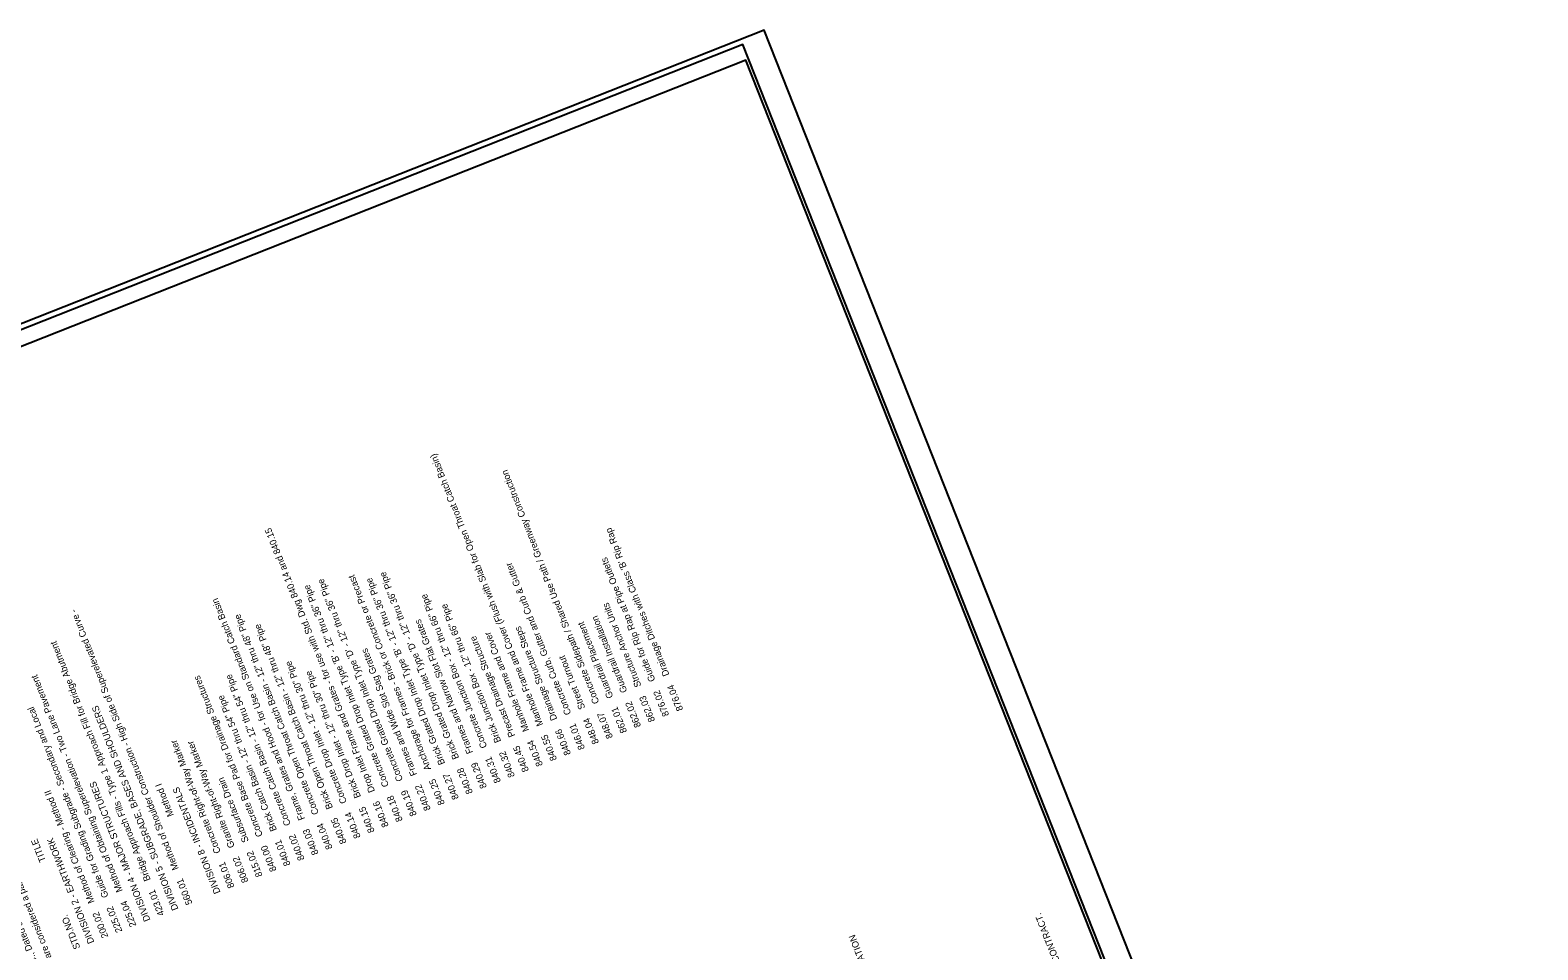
# Model space of a CAD drawing. Extents: x 1247235 to 1260080, y 742320 to 754020.
# Drawn here: x 1254628 to 1260080, y 750692 to 754020 of the extents above; entities that cross this region are included whole.
import ezdxf

# ---------------------------------------------------------------- set-up
doc = ezdxf.new("R2010")
doc.units = 0
for name, color, linetype in [('Scratch_Level_2', 7, 'Continuous'), ('Sheet Data Text CELL', 7, 'Continuous'), ('Sheet Plan CELL', 7, 'Continuous'), ('Sheet Plot Border Inside CELL', 7, 'Continuous'), ('Sheet Plot Border Outside CELL', 7, 'Continuous')]:
    doc.layers.add(name, color=color, linetype=linetype)

msp = doc.modelspace()

# ---------------------------------------------------------------- linework, layer by layer
at = {"layer": 'Scratch_Level_2'}
msp.add_line((1258461.9, 750758.6), (1257215.2, 753911.5), dxfattribs=at)
at = {"layer": 'Sheet Plan CELL'}
msp.add_lwpolyline([(1252801.2, 752166.1), (1255294.6, 745860.4), (1259708.5, 747605.8), (1257215.2, 753911.5)], close=True, dxfattribs=at)
at = {"layer": 'Sheet Plot Border Inside CELL'}
msp.add_lwpolyline([(1259974.2, 746964.6), (1257204.9, 753968.2), (1252769.9, 752214.5), (1255539.2, 745211)], close=True, dxfattribs=at)
at = {"layer": 'Sheet Plot Border Outside CELL'}
msp.add_lwpolyline([(1260079.9, 746943.2), (1257281.5, 754020.3), (1252678.4, 752200.2), (1255476.7, 745123.1)], close=True, dxfattribs=at)

# ---------------------------------------------------------------- texts
at = {"layer": 'Sheet Data Text CELL'}
for s, p in [('840.55    Manhole Frame and Cover (Flush with Slab for Open Throat Catch Basin)', (1256533.1, 751381.8)), ('848.07    Concrete Sidepath / Shared Use Path / Greenway Construction', (1256735.9, 751462)), ('840.16    Drop Inlet Frame and Grates - for use with Std. Dwg 840.14 and 840.15', (1255924.7, 751141.2)), ("876.04    Drainage Ditches with Class 'B' Rip Rap", (1256989.4, 751562.2)), ('876.02    Guide for Rip Rap at Pipe Outlets', (1256938.7, 751542.2)), ('840.25    Anchorage for Frames - Brick or Concrete or Precast', (1256127.5, 751221.4)), ('840.28    Brick Grated Drop Inlet Type \'D\' - 12" thru 36" Pipe', (1256228.9, 751261.5)), ('846.01    Concrete Curb, Gutter and Curb & Gutter', (1256634.5, 751421.9)), ('840.18    Concrete Grated Drop Inlet Type \'B\' - 12" thru 36" Pipe', (1255975.4, 751161.3)), ('840.19    Concrete Grated Drop Inlet Type \'D\' - 12" thru 36" Pipe', (1256026.1, 751181.3)), ('840.27    Brick Grated Drop Inlet Type \'B\' - 12" thru 36" Pipe', (1256178.2, 751241.5)), ('840.03    Frame, Grates and Hood - for Use on Standard Catch Basin', (1255671.2, 751041)), ('840.31    Concrete Junction Box - 12" thru 66" Pipe', (1256330.3, 751301.6)), ('840.32    Brick Junction Box - 12" thru 66" Pipe', (1256381, 751321.6)), ('862.03    Structure Anchor Units', (1256888, 751522.1)), ('560.01    Method of Shoulder Construction - High Side of Superelevated Curve - ', (1255214.9, 750860.6)), ('840.04    Concrete Open Throat Catch Basin - 12" thru 48" Pipe', (1255721.9, 751061)), ('840.29    Frames and Narrow Slot Flat Grates', (1256279.6, 751281.5)), ('862.01    Guardrail Placement', (1256786.6, 751482)), ('862.02    Guardrail Installation', (1256837.3, 751502.1)), ('840.05    Brick Open Throat Catch Basin - 12" thru 48" Pipe', (1255772.6, 751081.1)), ('840.45    Precast Drainage Structure', (1256431.7, 751341.7)), ('840.54    Manhole Frame and Cover', (1256482.4, 751361.7)), ('840.66    Drainage Structure Steps', (1256583.8, 751401.8)), ('423.01    Bridge Approach Fills - Type 1 Approach Fill for Bridge Abutment', (1255113.5, 750820.5)), ('840.22    Frames and Wide Slot Sag Grates', (1256076.8, 751201.4)), ('C., Dated January 16, 2024 are applicable to this project and by reference hereby ', (1254654.8, 750646.2)), ('840.14    Concrete Drop Inlet - 12" thru 30" Pipe', (1255823.3, 751101.1)), ('848.04    Street Turnout', (1256685.2, 751441.9)), ('225.04    Method of Obtaining Superelevation - Two Lane Pavement ', (1255012.1, 750780.4)), ('840.00    Concrete Base Pad for Drainage Structures', (1255519.1, 750980.8)), ('840.02    Concrete Catch Basin - 12" thru 54" Pipe', (1255620.5, 751020.9)), ('840.15    Brick Drop Inlet - 12" thru 30" Pipe', (1255874, 751121.2)), ('840.01    Brick Catch Basin - 12" thru 54" Pipe', (1255569.8, 751000.9)), ('225.02    Guide for Grading Subgrade - Secondary and Local', (1254961.4, 750760.3)), ('DIVISION 5 - SUBGRADE, BASES AND SHOULDERS', (1255164.2, 750840.5)), ('806.01    Concrete Right-of-Way Marker', (1255367, 750920.7)), ('806.02    Granite Right-of-Way Marker', (1255417.7, 750940.7)), ('DIVISION 4 - MAJOR STRUCTURES', (1255062.8, 750800.4)), ('Method I', (1255147.4, 751179.7)), ('DIVISION 8 - INCIDENTALS', (1255316.3, 750900.7)), ('815.02    Subsurface Drain', (1255468.4, 750960.8)), ('200.02    Method of Clearing - Method II', (1254910.7, 750740.3)), ('are considered a part of these plans:', (1254705.5, 750666.2)), ('STD.NO.                       TITLE', (1254809.3, 750700.2)), ('DIVISION 2 - EARTHWORK', (1254860, 750720.2)), ('         ALL RIGHT-OF-WAY MARKERS ON THIS PROJECT SHALL BE PLACED BY CONTRACT.  ', (1258801, 749515.4)), ('         SECTION PRIOR TO SETTING OF THE SLOPE STAKES FOR THE EMBANKMENT OR EXCAVATION ', (1258192.7, 749274.9))]:
    msp.add_text(s, height=24.23, rotation=111.5743, dxfattribs=at).set_placement(p)

doc.saveas('drawing.dxf')
